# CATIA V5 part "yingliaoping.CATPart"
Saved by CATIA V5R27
Part number: 可乐饮料瓶
Material "Pastel Green": density 7860 kg/m3, Young's modulus 2e+11 Pa, Poisson ratio 0.266
Bounding box of the stored display mesh (mm): x -1067.831 to 50, y -50 to 0, z 0 to 450.341
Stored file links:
  H:\180131229fjz.CATPart
  H:\Part2.CATPart
  e:\Program Files\Dassault Systemes\B17\intel_a\startup\materials\Simplified_Chinese\Catalog.CATMaterial
  E:\Program Files\Dassault Systemes\B27\win_b64\startup\materials\DS_star.jpg
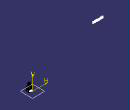
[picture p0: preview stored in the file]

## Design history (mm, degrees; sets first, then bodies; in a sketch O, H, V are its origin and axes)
Set1 "几何图形集.1"
  Point1: type OnCurve, Support edge [face of Pad1 from Sketch11.L1 | face of Pad1 from Sketch11.L2], Ratio 0.5
  Point2: type OnCurve, Support edge [face of Pad1 from Sketch11.L2 | face of Pad1 from Sketch11.L3], Ratio 0.5
  Point3: type OnCurve, Support edge [face of Pad1 from Sketch11.L3 | face of Pad1 from Sketch11.L4], Ratio 0.5
  Point4: type OnCurve, Support edge [face of Pad1 from Sketch11.L4 | face of Pad1 from Sketch11.L1], Ratio 0.5
  Point5: type OnCurve, Support edge [start face of Pad1 | face of Pad1 from Sketch11.L2], Ratio 0.5
  Point6: type OnCurve, Support edge [start face of Pad1 | face of Pad1 from Sketch11.L3], Ratio 0.5
  Point7: type OnCurve, Support edge [start face of Pad1 | face of Pad1 from Sketch11.L4], Ratio 0.5
  Point8: type OnCurve, Support edge [start face of Pad1 | face of Pad1 from Sketch11.L1], Ratio 0.5
  Plane1: type Offset, RefPlane end face of Pad1, Offset 40, reversed
  Point9: type OnCurve, Support edge [face of Pad1 from Sketch11.L1 | end face of Pad1], Ratio 0.5
  Sketch1 "草图.3" on start face of Pad2, origin (0, 0, 90), H (1, 0, 0), V (0, -1, 0)
    point P1 (25, 10)
    reference projected circle E1 centre (25, 25) radius 15 from edge [face of Pad2 from Sketch12.A1 | start face of Pad2]
    distance P1 V = 25
    coincidence: P1 E1
  Boundary1: Boundary {extract ExtractElem end face of Pad1}
  Boundary2: Boundary {extract ExtractElem start face of Pad2}
  Sketch2 "草图.4" on face of Pad1 from Sketch11.L2, origin (50, 0, 0), H (0, 1, 0), V (0, 0, 1)
    spline S1 through (-55, 35) (-30, 30) (-15, 35) (15, 30)
    point P1 (15, 30)
    point P2 (-15, 35)
    point P3 (-30, 30)
    point P4 (-55, 35)
    distance P1 V = 15
    distance P2 V = 15
    distance P1 H = 30
    distance P3 H = 30
    distance P3 V = 30
    distance P2 H = 35
    distance P4 H = 35
    distance P4 V = 55
  Extrude1: Element1 Sketch2, Lim1 50, Lim2 0
  MultiSel1
  Join1: Elements ({intersect ToIntersect1 Extrude1, ToIntersect2 {extract ExtractElem face of Fillet1}}; {intersect ToIntersect1 Extrude1, ToIntersect2 {extract ExtractElem face of Pad1 from Sketch11.L3}}; {intersect ToIntersect1 Extrude1, ToIntersect2 {extract ExtractElem face of Fillet1}}; {intersect ToIntersect1 Extrude1, ToIntersect2 {extract ExtractElem face of Pad1 from Sketch11.L2}}; {intersect ToIntersect1 Extrude1, ToIntersect2 {extract ExtractElem face of Fillet1}}; {intersect ToIntersect1 Extrude1, ToIntersect2 {extract ExtractElem face of Pad1 from Sketch11.L1}}; {intersect ToIntersect1 Extrude1, ToIntersect2 {extract ExtractElem face of Fillet1}}; {intersect ToIntersect1 Extrude1, ToIntersect2 {extract ExtractElem face of Pad1 from Sketch11.L4}})
  Plane2: type Offset, RefPlane yz-plane, Offset 25
  Sketch3 on Plane2, origin (25, 0, 0), H (0, 1, 0), V (0, 0, 1)
    circle A1 centre (1, 36.455) radius 2
    point P1 (1, 36.455)
    reference projected point E1 (0, 36.455) from vertex [face of MultiSel1 | face of MultiSel1]
    reference projected point E2 (0, 36.455) from vertex [face of MultiSel1 | face of MultiSel1]
    radius A1 = 2
    distance P1 E1 H = 1
    distance P1 E2 V = 0
  Translate1: ToTransfor Extrude1, Direction (0, 0, 1), Length 15
  MultiSel2
  Join2: Elements ({intersect ToIntersect1 Translate1, ToIntersect2 {extract ExtractElem face of Loft1}}; {intersect ToIntersect1 Translate1, ToIntersect2 {extract ExtractElem face of Loft1}}; {intersect ToIntersect1 Translate1, ToIntersect2 {extract ExtractElem face of Pad1 from Sketch11.L2}}; {intersect ToIntersect1 Translate1, ToIntersect2 {extract ExtractElem face of Fillet1}}; {intersect ToIntersect1 Translate1, ToIntersect2 {extract ExtractElem face of Pad1 from Sketch11.L3}}; {intersect ToIntersect1 Translate1, ToIntersect2 {extract ExtractElem face of Fillet1}}; {intersect ToIntersect1 Translate1, ToIntersect2 {extract ExtractElem face of Pad1 from Sketch11.L4}}; {intersect ToIntersect1 Translate1, ToIntersect2 {extract ExtractElem face of Loft1}}; {intersect ToIntersect1 Translate1, ToIntersect2 {extract ExtractElem face of Loft1}}; {intersect ToIntersect1 Translate1, ToIntersect2 {extract ExtractElem face of Loft1}})
  Sketch4 on Plane2, origin (25, 0, 0), H (0, 1, 0), V (0, 0, 1)
    circle A1 centre (-51, 47.0591) radius 2
    point P1 (-51, 47.0591)
    reference projected point E1 (-50, 47.0591) from vertex [face of MultiSel2 | face of MultiSel2]
    reference projected point E2 (-50, 47.0591) from vertex [face of MultiSel2 | face of MultiSel2]
    distance P1 E1 H = 1
    radius A1 = 2
    distance E2 P1 V = 0
  Point10: (25, -10, 94)
  Point11: (25, -25, 110)
  Line1: type PtDir, RefPoint Point11, Direction (0, 0, 1), Start 0, End 20
  Helix1: Direction Line1, RefPoint Point10, Pitch 3, Height 15, TaperAngle 0
  Line2: type PtDir, RefPoint Point10, Direction (0, 1, 0), Start 0, End 2
  Point12: type OnCurve, Support Helix1, Length 2
  Connect1: Curve1 Helix1, Point1 Point12, Tension1 1, Curve2 Line2, Point2 vertex of Line2, Tension2 1
  Line3: type PtDir, RefPoint vertex of Helix1, Direction (0, 1, 0), Start 0, End 2
  Point13: type OnCurve, Support Connect1, Length 2
  Connect2: Curve1 Line3, Point1 vertex of Line3, Tension1 1, Curve2 Connect1, Point2 Point13, Tension2 1
  Circle1: type CtrRad, Start 0, End 180, Center vertex of Connect1, Support {plane type OffsetPt, RefPlane zx-plane, RefPoint vertex of Connect1}, Radius 1, FirstDirection (-1, 0, 0)
Set2 "几何图形集.2"
  Sketch5 on xy-plane, origin (0, 0, 0), H (1, 0, 0), V (0, 1, 0)
    line L1 (48, -48) -> (2, -48)
    line L2 (48, -2) -> (48, -48)
    line L3 (2, -48) -> (2, -2)
    point P1 (2, -2)
    line L4 (2, -2) -> (48, -2)
    distance L2 L3 = 46
    distance L4 L1 = 46
    distance P1 H = 2
    distance P1 V = 2
    horizontal: L1 H, L4 H
    vertical: L2 V, L3 V
    perpendicularity: L4 L2
  Point14: type OnCurve, Support edge [face of Pad3 from Sketch5.L3 | face of Pad3 from Sketch5.L4], Ratio 0.5
  Point15: type OnCurve, Support edge [face of Pad3 from Sketch5.L1 | face of Pad3 from Sketch5.L3], Ratio 0.5
  Point16: type OnCurve, Support edge [face of Pad3 from Sketch5.L4 | face of Pad3 from Sketch5.L2], Ratio 0.5
  Point17: type OnCurve, Support edge [face of Pad3 from Sketch5.L2 | face of Pad3 from Sketch5.L1], Ratio 0.5
  Point18: type OnCurve, Support edge [start face of Pad3 | face of Pad3 from Sketch5.L3], Ratio 0.5
  Point19: type OnCurve, Support edge [start face of Pad3 | face of Pad3 from Sketch5.L4], Ratio 0.5
  Point20: type OnCurve, Support edge [start face of Pad3 | face of Pad3 from Sketch5.L2], Ratio 0.5
  Point21: type OnCurve, Support edge [start face of Pad3 | face of Pad3 from Sketch5.L1], Ratio 0.5
  Sketch6 on Plane1, origin (0, 0, 90), H (1, 0, 0), V (0, -1, 0)
    circle A1 centre (25, 25) radius 13
    point P1 (25, 25)
    radius A1 = 13
    distance P1 H = 25
    distance V P1 = 25
  Point22: type OnCurve, Support edge [face of Pad3 from Sketch5.L4 | end face of Pad3], Ratio 0.5
  Sketch7 on start face of Pad4, origin (0, 0, 90), H (1, 0, 0), V (0, -1, 0)
    point P1 (25, 12)
    reference projected circle E1 centre (25, 25) radius 13 from edge [face of Pad4 from Sketch6.A1 | start face of Pad4]
    distance P1 V = 25
    coincidence: P1 E1
  Boundary3: Boundary {extract ExtractElem start face of Pad4}
  Boundary4: Boundary {extract ExtractElem end face of Pad3}
  MultiSel3
  Join3: Elements ({intersect ToIntersect1 Extrude1, ToIntersect2 {extract ExtractElem face of Fillet4}}; {intersect ToIntersect1 Extrude1, ToIntersect2 {extract ExtractElem face of Pad3 from Sketch5.L3}}; {intersect ToIntersect1 Extrude1, ToIntersect2 {extract ExtractElem face of Fillet4}}; {intersect ToIntersect1 Extrude1, ToIntersect2 {extract ExtractElem face of Pad3 from Sketch5.L4}}; {intersect ToIntersect1 Extrude1, ToIntersect2 {extract ExtractElem face of Fillet4}}; {intersect ToIntersect1 Extrude1, ToIntersect2 {extract ExtractElem face of Pad3 from Sketch5.L2}}; {intersect ToIntersect1 Extrude1, ToIntersect2 {extract ExtractElem face of Fillet4}}; {intersect ToIntersect1 Extrude1, ToIntersect2 {extract ExtractElem face of Pad3 from Sketch5.L1}})
  MultiSel4
  Join4: Elements ({intersect ToIntersect1 Translate1, ToIntersect2 {extract ExtractElem face of Pad3 from Sketch5.L2}}; {intersect ToIntersect1 Translate1, ToIntersect2 {extract ExtractElem face of Loft2}}; {intersect ToIntersect1 Translate1, ToIntersect2 {extract ExtractElem face of Loft2}}; {intersect ToIntersect1 Translate1, ToIntersect2 {extract ExtractElem face of Loft2}}; {intersect ToIntersect1 Translate1, ToIntersect2 {extract ExtractElem face of Loft2}}; {intersect ToIntersect1 Translate1, ToIntersect2 {extract ExtractElem face of Pad3 from Sketch5.L3}}; {intersect ToIntersect1 Translate1, ToIntersect2 {extract ExtractElem face of Fillet4}}; {intersect ToIntersect1 Translate1, ToIntersect2 {extract ExtractElem face of Pad3 from Sketch5.L1}}; {intersect ToIntersect1 Translate1, ToIntersect2 {extract ExtractElem face of Fillet4}}; {intersect ToIntersect1 Translate1, ToIntersect2 {extract ExtractElem face of Loft2}})
  Sketch8 on Plane2, origin (25, 0, 0), H (0, 1, 0), V (0, 0, 1)
    circle A1 centre (-1, 36.6906) radius 2
    point P1 (-1, 36.6906)
    reference projected point E1 (-2, 36.6906) from vertex [face of MultiSel3 | face of MultiSel3]
    reference projected point E2 (-2, 36.6906) from vertex [face of MultiSel3 | face of MultiSel3]
    radius A1 = 2
    distance P1 E1 H = 1
    distance P1 E2 V = 0
  Sketch9 on Plane2, origin (25, 0, 0), H (0, 1, 0), V (0, 0, 1)
    circle A1 centre (-49, 46.1561) radius 2
    point P1 (-49, 46.1561)
    reference projected point E1 (-48, 46.1561) from vertex [face of MultiSel4 | face of MultiSel4]
    reference projected point E2 (-48, 46.1561) from vertex [face of MultiSel4 | face of MultiSel4]
    radius A1 = 2
    distance P1 E1 H = 1
    distance P1 E2 V = 0
  Sketch10 on face of Pad1 from Sketch11.L3, origin (0, -50, 0), H (1, 0, 0), V (0, 0, 1)
    polyline C1
    polyline C2
    polyline C3
    polyline C4
    polyline C5
    polyline C6
    polyline C7
    polyline C8
    polyline C9
    polyline C10
    polyline C11
    polyline C12
    polyline C13
    polyline C14
Body1 (main body), material "Pastel Green"
  Sketch11 on xy-plane, origin (0, 0, 0), H (1, 0, 0), V (0, 1, 0)
    line L1 (0, 0) -> (50, 0)
    line L2 (50, 0) -> (50, -50)
    line L3 (50, -50) -> (0, -50)
    line L4 (0, -50) -> (0, 0)
    length L2 = 50
    length L3 = 50
    horizontal: L1 H, L3 H
    vertical: L2 V, L4 V
  Pad1: profile Sketch11, direction (0, 0, 1), length 50
  Fillet1: on edge [face of Pad1 from Sketch11.L1 | face of Pad1 from Sketch11.L2]; edge [face of Pad1 from Sketch11.L2 | face of Pad1 from Sketch11.L3]; edge [face of Pad1 from Sketch11.L3 | face of Pad1 from Sketch11.L4]; edge [face of Pad1 from Sketch11.L4 | face of Pad1 from Sketch11.L1]
  Fillet2: on edge [start face of Pad1 | face of Fillet1] (x4); edge [start face of Pad1 | face of Pad1 from Sketch11.L2]; edge [start face of Pad1 | face of Pad1 from Sketch11.L3]; edge [start face of Pad1 | face of Pad1 from Sketch11.L4]; edge [start face of Pad1 | face of Pad1 from Sketch11.L1]
  Sketch12 on Plane1, origin (0, 0, 90), H (1, 0, 0), V (0, -1, 0)
    circle A1 centre (25, 25) radius 15
    point P1 (25, 25)
    radius A1 = 15
    distance P1 H = 25
    distance P1 V = 25
  Pad2: profile Sketch12, direction (0, 0, 1), length 20
  Loft1: solid, Sections (Boundary1; Boundary2), StartFace end face of Pad1, EndFace start face of Pad2
  Slot1: profile Sketch3, centre curve Join1
  Slot2: profile Sketch4, centre curve Join2
  Fillet3: radius 1, on edge [face of Fillet1 | face of Slot1] (x3); edge [face of Slot1 | face of Fillet1] (x4); edge [face of Fillet1 | face of Slot2] (x3); edge [face of Loft1 | face of Slot2] (x2); edge [face of Slot2 | face of Fillet1] (x3); edge [face of Slot2 | face of Pad1 from Sketch11.L1]; edge [face of Pad1 from Sketch11.L4 | face of Slot2]; edge [face of Pad1 from Sketch11.L3 | face of Slot2]; edge [face of Slot2 | face of Pad1 from Sketch11.L3]; edge [face of Slot2 | face of Loft1]
  Rib1: profile Circle1, centre curve Connect2
  Body2
    Pad3: profile Sketch5, direction (0, 0, 1), length 50, opposite side length -2
    Fillet4: on edge [face of Pad3 from Sketch5.L4 | face of Pad3 from Sketch5.L2]; edge [face of Pad3 from Sketch5.L2 | face of Pad3 from Sketch5.L1]; edge [face of Pad3 from Sketch5.L3 | face of Pad3 from Sketch5.L4]; edge [face of Pad3 from Sketch5.L1 | face of Pad3 from Sketch5.L3]
    Fillet5: on edge [start face of Pad3 | face of Fillet4] (x4); edge [start face of Pad3 | face of Pad3 from Sketch5.L4]; edge [start face of Pad3 | face of Pad3 from Sketch5.L2]; edge [start face of Pad3 | face of Pad3 from Sketch5.L1]; edge [start face of Pad3 | face of Pad3 from Sketch5.L3]
    Pad4: profile Sketch6, direction (0, 0, 1), length 20
    Loft2: solid, Sections (Boundary3; Boundary4), StartFace start face of Pad4, EndFace end face of Pad3
    Slot3: profile Sketch8, centre curve Join3
    Slot4: profile Sketch9, centre curve Join4
  Remove1: tool Body2
Body3
  Sketch13 on face of Pad1 from Sketch11.L1, origin (0, 0, 0), H (-1, 0, 0), V (0, 0, 1)
    polyline C1
    polyline C2
    polyline C3
    polyline C4
    polyline C5
    polyline C6
    polyline C7
    polyline C8
    polyline C9
    polyline C10
    polyline C11
    polyline C12
    polyline C13
    polyline C14
    polyline C15
    polyline C16
    polyline C17
    polyline C18
    polyline C19
    polyline C20
    polyline C21
    polyline C22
